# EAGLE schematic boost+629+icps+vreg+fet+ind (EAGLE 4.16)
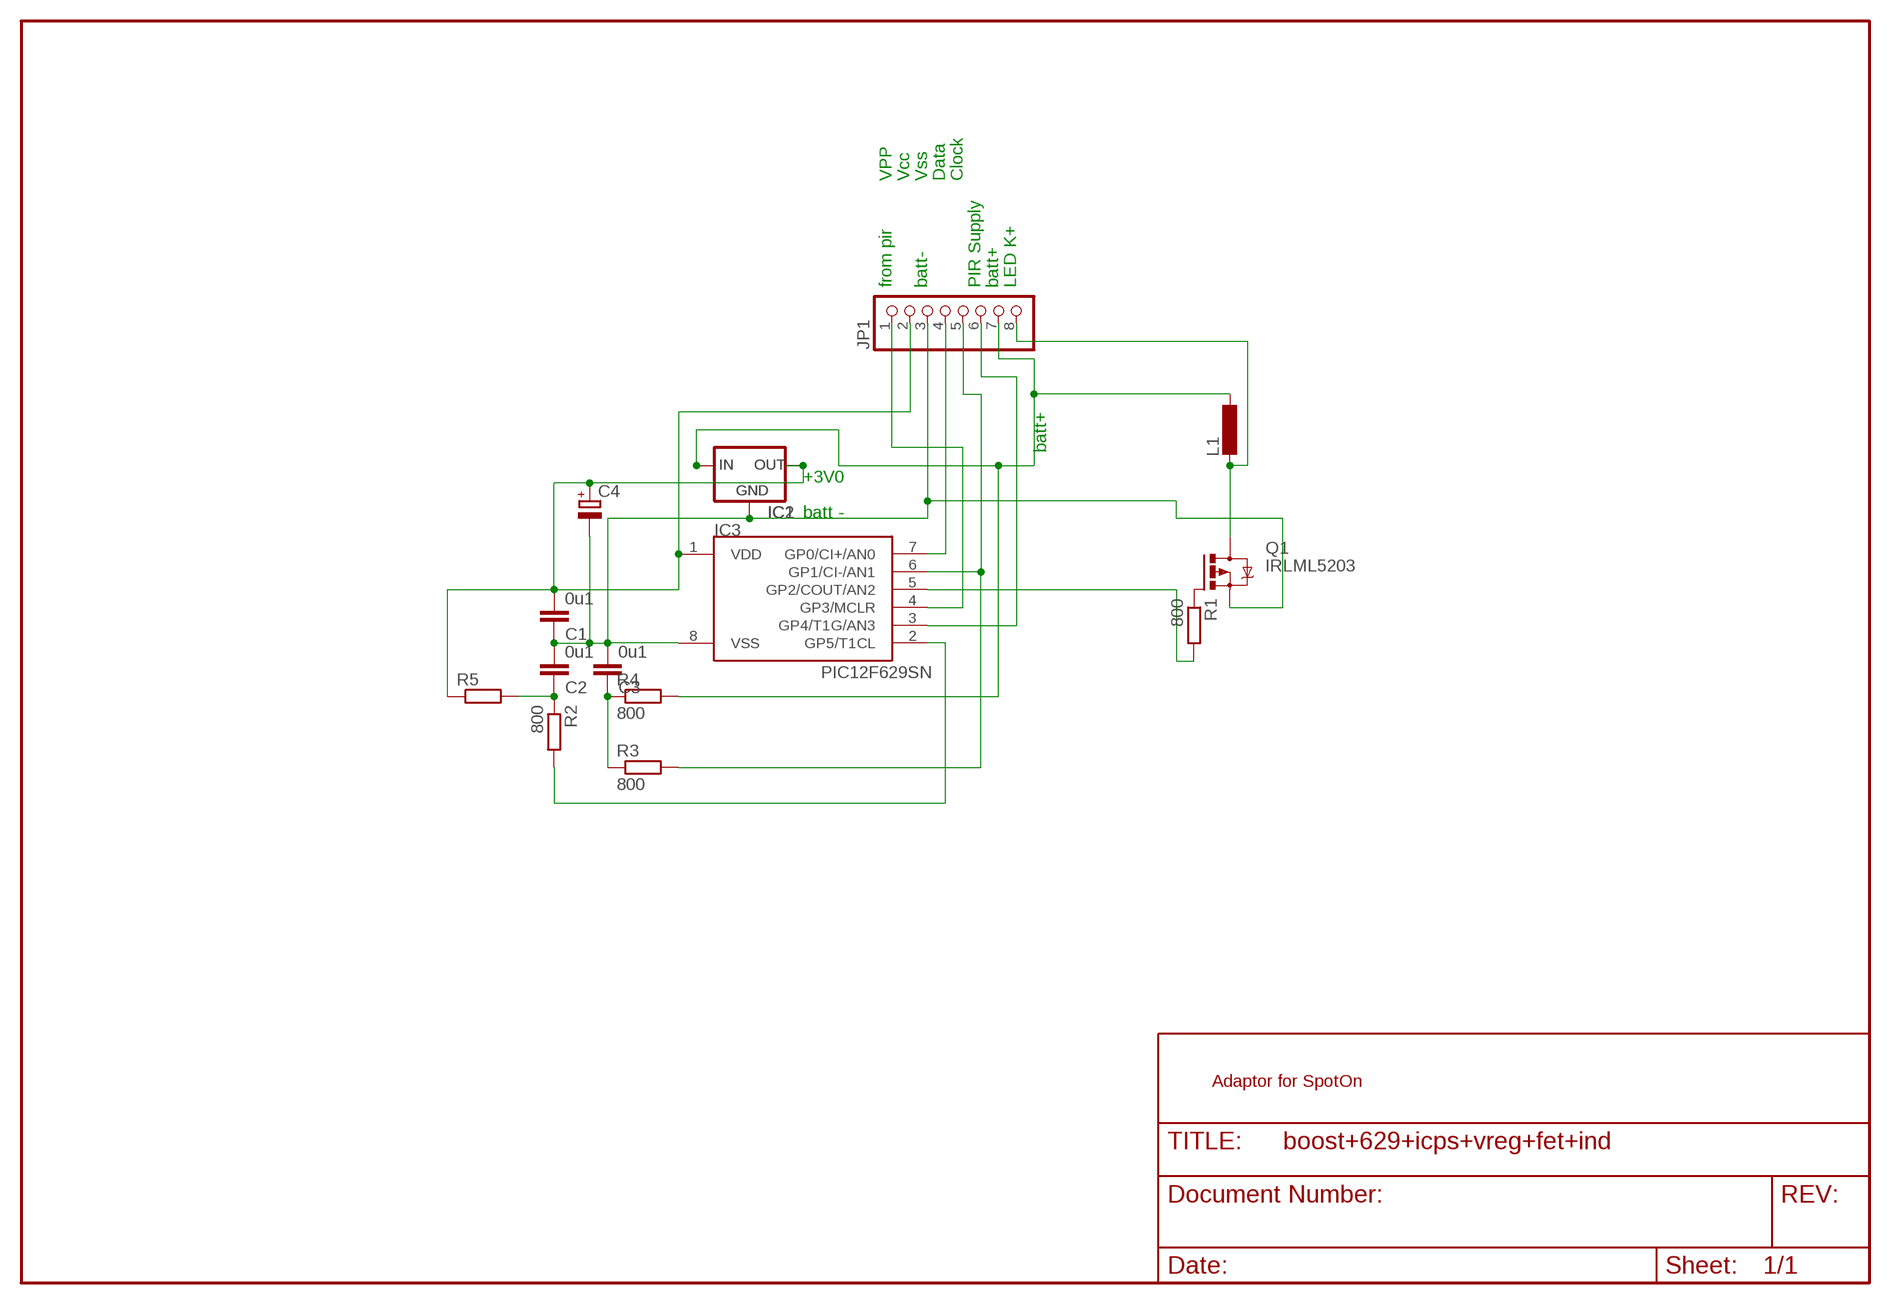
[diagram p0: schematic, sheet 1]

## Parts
C1  0u1  C-EUC1206  [C1206]
C2  0u1  C-EUC1206  [C1206]
C3  0u1  C-EUC1206  [C1206]
C4  CPOL-EUE2.5-6  [E2,5-6]
IC1  XC63FPP  [SOT89R]
IC2  XC63FPT  [TO92]
IC3  PIC12F629SN  [SO-08]
JP1  PINHD-1X8  [1X08]
L1  L-EU2200-11.43  [2200-11.43]
Q1  IRLML5203  [MICRO3]
R1  800  R-EU_R1206  [R1206]
R2  800  R-EU_R1206  [R1206]
R3  800  R-EU_R1206  [R1206]
R4  800  R-EU_R1206  [R1206]
R5  R-EU_0411/3V  [0411V]

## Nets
N$1: C1.1 C2.2 C3.2 C4.- IC1.1(GND) IC2.1(GND) IC3.8(VSS) JP1.3 Q1.2(S)
N$2: IC3.2(GP5/T1CL) R2.2
N$3: IC1.2(IN) IC2.2(IN) JP1.7 L1.1 R4.2
N$4: IC3.6(GP1/CI-/AN1) JP1.5 R3.2
N$5: JP1.8 L1.2 Q1.3(D)
N$6: C1.2 C4.+ IC1.3(OUT) IC2.3(OUT) IC3.1(VDD) JP1.2 R5.1
N$7: C3.1 R3.1 R4.1
N$9: IC3.4(GP3/MCLR) JP1.1
N$11: C2.1 R2.1 R5.2
N$12: Q1.1(G) R1.1
N$14: IC3.7(GP0/CI+/AN0) JP1.4
N$16: IC3.5(GP2/COUT/AN2) R1.2
N$17: IC3.3(GP4/T1G/AN3) JP1.6

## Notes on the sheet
- VPP | Vcc | Vss | Data | Clock
- from pir | batt- | PIR Supply | batt+ | LED K+
- batt+
- +3V0
- batt -
- Adaptor for SpotOn

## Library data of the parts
C1-C3 = rcl:C-EU: CAPACITOR, European symbol
C4 = rcl(2):CPOL-EU: POLARIZED CAPACITOR, European symbol
IC1 IC2 = v-reg:XC63FP: Positiv Voltage Regulators www.torex.co.jp/english/product/pro02/pdf/0201_xc62fp.pdf
IC3 = microchip-3:PIC12F6*: uPC nW 1k Program Flash memory 2x Timer Comparator 10b A/D converter/ 4xIN
JP1 = pinhead(2):PINHD-1X8: PIN HEADER
L1 = rcl:L-EU: INDUCTOR, European symbol
Q1 = transistor-power:IRLML5203: HEXFET P-Channel Power MOSFET
R1-R5 = rcl:R-EU_: RESISTOR, European symbol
